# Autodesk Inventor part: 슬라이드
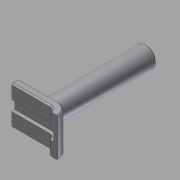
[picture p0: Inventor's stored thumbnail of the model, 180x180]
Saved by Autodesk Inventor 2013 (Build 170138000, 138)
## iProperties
Created: 2015-10
Part Number: 슬라이드
Document SubType Name: Modeling
Designer: mdu
Density: 1 g/cm^3
Material: 강철, 연강
Mass: 2.71806 g
Surface Area: 19.6411 cm^2
Volume: 2.71806 cm^3
Author: mdu
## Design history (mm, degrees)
sketch "스케치1"
  geometry: L1 (10.279, 23.212)-(25.279, 23.212); L2 (10.279, 19.212)-(25.279, 19.212); L3 (25.279, 26.212)-(10.279, 26.212); L4 (10.279, 26.212)-(10.279, 16.212); L5 (10.279, 16.212)-(25.279, 16.212); C1 r 2 at (25.279, 21.212); A1 r 2 centre (25.279, 21.212) between (25.279, 23.212) and (25.279, 19.212) reference; A2 r 5 centre (25.279, 21.212) between (25.279, 26.212) and (25.279, 16.212); 1 further point
  constraints: 10 end point, 4 point on circle, 4 tangent, 3 parallel, 2 centre point, 2 coincident, 2 point on line, 1 horizontal, 1 perpendicular
  dimensions: "d0" = 4 diameter of C1; "d1" = 10 diameter of A2; "d4" = 15 distance from line of A2.centre L4
extrude "돌출1" new body sketch "스케치1" stored distance "d2" = 15; taper "d3" = 0 deg
sketch "스케치2"
  geometry: L1 (10.279, 26.212)-(10.279, 23.212) reference; L2 (10.279, 24.462)-(25.279, 24.462); L3 (27.779, 19.135)-(27.779, 6.212); L4 (27.779, 6.212)-(0.279, 6.212); L5 (0.279, 6.212)-(0.279, 24.462); L6 (10.279, 24.462)-(0.279, 24.462); A1 r 5 centre (25.279, 21.212) between (25.279, 16.212) and (25.279, 26.212) reference; A2 r 3.25 centre (25.279, 21.212) between (25.279, 24.462) and (27.779, 19.135); 1 further point
  constraints: 10 end point, 4 perpendicular, 2 point on circle, 1 centre point, 1 coincident, 1 parallel, 1 point on line, 1 tangent
  dimensions: "d5" = 6.5 diameter of A2; "d6" = 10 distance between parallel lines of L1 L5; "d7" = 10 distance from line of L4 A1.start; "d8" = 2.5 distance from line of L3 A1.centre
extrude "돌출2" cut sketch "스케치2" stored distance "d9" = 4; taper "d10" = 0 deg
sketch "스케치3"
  geometry: L1 (0, 15)-(0, 0) reference; C1 r 4 at (9.5, 7.5); 2 further points
  constraints: 1 centre point, 1 horizontal alignment, 1 midpoint
  dimensions: "d11" = 8 diameter of C1; "d12" = 9.5 distance from line of C1.centre L1
extrude "돌출3" join sketch "스케치3" distance "d13" = 40; taper "d14" = 0 deg
sketch "스케치4"
  geometry: C1 r 4 at (9.5, 7.5) reference; C2 r 4.65 at (9.5, 7.5); C3 r 6.75 at (9.5, 7.5); C4 r 5.5 at (9.5, 7.5); 1 further point
  constraints: 3 centre point, 3 coincident
  dimensions: "d15" = 9.3 diameter of C2; "d16" = 13.5 diameter of C3; "d19" = 11 diameter of C4
extrude "돌출4" cut sketch "스케치4" distance "d17" = 0.5; taper "d18" = 0 deg
sketch "스케치5"
  geometry: L1 (30.279, 21.212)-(7.279, 21.212); L2 (7.279, 21.212)-(7.279, 13.212); L3 (7.279, 13.212)-(31.947, 13.212); L4 (31.947, 13.212)-(31.947, 21.212); L5 (31.947, 21.212)-(30.279, 21.212); L6 (10.279, 16.212)-(10.279, 19.212) reference; A1 r 5 centre (25.279, 21.212) between (25.279, 16.212) and (25.279, 26.212) reference; 1 further point
  constraints: 10 end point, 2 perpendicular, 1 collinear, 1 horizontal, 1 parallel, 1 point on circle
  dimensions: "d20" = 3 distance between parallel lines of L2 L6; "d21" = 8 distance of L3.end L4.end
extrude "돌출5" cut sketch "스케치5" stored distance "d22" = 1; taper "d23" = 0 deg
chamfer "모따기1" distance "d24" = 0.5; stored, may be unused: second distance "d25" = 2, angle "d26" = 45 deg
hole "구멍1" diameter "d29" = 3.242; stored, may be unused: countersink angle "d33" = 90 deg, drill point angle "d35" = 118 deg; dims "d27" = 10, "d28" = 10, "d30" = 6, "d31" = 4, "d32" = 2, "d34" = 8
chamfer "모따기2" distance "d36" = 0.5; stored, may be unused: second distance "d37" = 2, angle "d38" = 45 deg
node "솔리드1"
node "참조1"
node "투영된 루프1"
